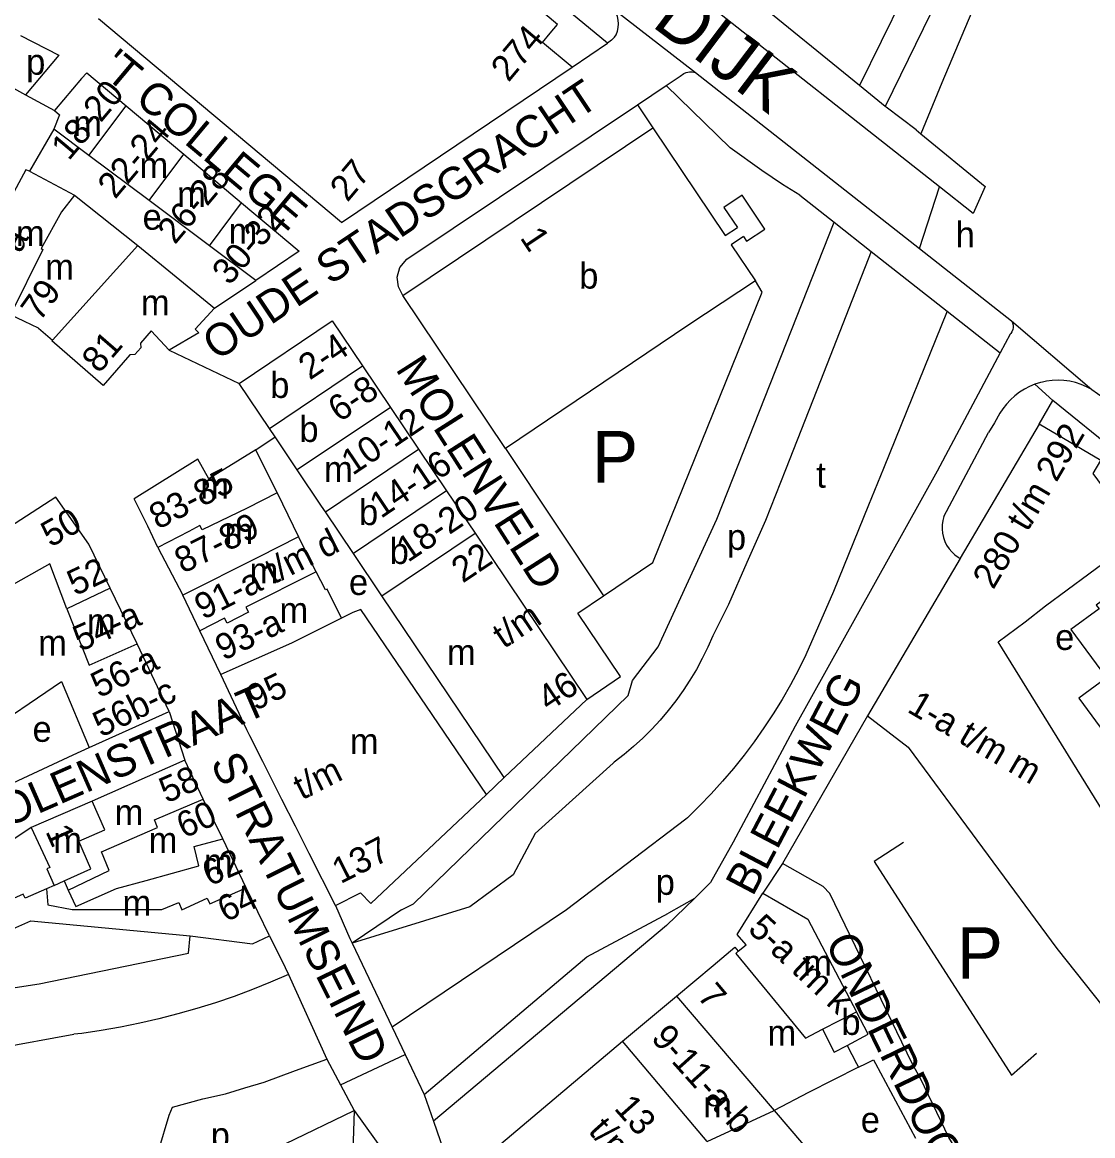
# Model space of a CAD drawing. Extents: x 160673 to 161924, y 382258 to 384145.
# Drawn here: x 161632.6 to 161798.8, y 382888.8 to 383061.6 of the extents above; entities that cross this region are included whole.
import ezdxf

# ---------------------------------------------------------------- set-up
doc = ezdxf.new("R2010")
doc.units = 0
for name, color, linetype in [('BLT_Basislijn', 7, 'Continuous'), ('BLT_Bebouwing', 7, 'Continuous'), ('BLT_Centroide', 7, 'Continuous'), ('BLT_Huisnummer', 7, 'Continuous'), ('BLT_Huisnummer_reeks', 7, 'Continuous'), ('BLT_Onderverdeling_panden', 7, 'Continuous'), ('BLT_Straatnaam', 7, 'Continuous'), ('BLT_Straatnaam_hoofdweg', 7, 'Continuous'), ('BLT_Tekst_parkeren', 7, 'Continuous'), ('BLT_Vlakafsluiter', 7, 'Continuous')]:
    doc.layers.add(name, color=color, linetype=linetype)

msp = doc.modelspace()

# ---------------------------------------------------------------- linework, layer by layer
at = {"layer": 'BLT_Basislijn'}
for p, q in [((161802.97, 383122.97), (161766.55, 383048.54)), ((161774.99, 383036.07), (161709.02, 383088.14)), ((161762.58, 383051.8), (161724.31, 383082.94)), ((161771.33, 383069.65), (161762.58, 383051.8)), ((161632.34, 383059.58), (161638.3, 383056.5)), ((161724.11, 383058.83), (161723.47, 383058.38)), ((161638.3, 383056.5), (161633.15, 383050.37)), ((161737.11, 383053.84), (161771.92, 383026.48)), ((161728.12, 383048.78), (161732.6, 383051.78)), ((161732.6, 383051.78), (161734.76, 383053.23)), ((161766.55, 383048.54), (161762.58, 383051.8)), ((161775.34, 383052.22), (161772.1, 383044.3)), ((161728.12, 383048.78), (161730.52, 383045.21)), ((161766.7, 383048.42), (161766.55, 383048.54)), ((161771.37, 383044.9), (161766.7, 383048.42)), ((161771.37, 383044.9), (161772.1, 383044.3)), ((161772.1, 383044.3), (161782.07, 383036.13)), ((161753.31, 383034.77), (161758.65, 383030.57)), ((161780.23, 383031.93), (161774.99, 383036.07)), ((161758.65, 383030.57), (161764.42, 383026.04)), ((161764.42, 383026.04), (161756.54, 383005.95)), ((161764.42, 383026.04), (161776.19, 383016.8)), ((161771.92, 383026.48), (161786.16, 383015.29)), ((161662.45, 383017.23), (161668.89, 383021.56)), ((161776.19, 383016.8), (161766.3, 382992.38)), ((161776.19, 383016.8), (161784.44, 383010.33)), ((161785.96, 383013.2), (161784.44, 383010.33)), ((161784.44, 383010.33), (161774.64, 382991.92)), ((161792.59, 383002.89), (161789.82, 383005.44)), ((161790.49, 382999.25), (161792.59, 383002.89)), ((161812.15, 382987.08), (161792.59, 383002.89)), ((161668.87, 382995.25), (161671.87, 382997.26)), ((161775.68, 382984.89), (161782.63, 382997.93)), ((161707.66, 382995.45), (161722.86, 382972.59)), ((161655.45, 382954.64), (161657.87, 382947.06)), ((161763.84, 382953.98), (161750.63, 382931.05)), ((161640.54, 382947.93), (161643.01, 382949.05)), ((161631.24, 382943.54), (161640.54, 382947.93)), ((161704.68, 382941.78), (161707.42, 382944.41)), ((161634.03, 382936.61), (161604.03, 382916.71)), ((161750.63, 382931.05), (161747.57, 382926.46)), ((161737, 382925.62), (161732.92, 382923.36)), ((161681.23, 382924.54), (161683.5, 382919.4)), ((161670.99, 382919.84), (161673.46, 382914.91)), ((161683.5, 382919.4), (161683.83, 382918.7)), ((161683.83, 382918.7), (161690.05, 382905.65)), ((161673.46, 382914.91), (161673.96, 382913.83)), ((161673.96, 382913.83), (161679.92, 382900.69)), ((161690.05, 382905.65), (161692.07, 382901.4)), ((161613.51, 382899.59), (161640.65, 382904.53)), ((161682.04, 382896.68), (161692.07, 382901.4)), ((161692.07, 382901.4), (161695.03, 382895.19)), ((161679.92, 382900.69), (161682.04, 382896.68)), ((161682.04, 382896.68), (161684.14, 382892.71)), ((161695.03, 382895.19), (161696.46, 382891.05)), ((161696.46, 382891.05), (161699.83, 382881.27))]:
    msp.add_line(p, q, dxfattribs=at)
for points in [[(161819.83, 383149.18), (161820.21, 383146.13), (161819.64, 383142.5), (161818.55, 383140.46), (161815.64, 383134.73), (161812.46, 383129.75), (161808.28, 383124.28), (161804.19, 383116.19), (161791.81, 383089.44), (161781.57, 383066.96), (161775.34, 383052.22)], [(161723.47, 383058.38), (161712.3, 383067.64), (161706.21, 383072.34)], [(161724.11, 383058.83), (161724.56, 383059.31), (161724.83, 383059.69), (161725.03, 383060.23), (161725.15, 383060.79), (161725.19, 383061.36), (161725.15, 383061.94), (161725.03, 383062.5), (161724.83, 383063.04), (161724.52, 383063.62)], [(161717.99, 383054.63), (161723.47, 383058.38)], [(161734.76, 383053.23), (161735.32, 383053.65), (161735.69, 383053.8), (161736.2, 383053.9), (161736.59, 383053.93), (161737.11, 383053.84)], [(161753.31, 383034.77), (161750.63, 383036.42), (161747.43, 383038.59), (161742.51, 383042.14), (161732.6, 383051.78)], [(161691.7, 383019.23), (161691.01, 383020.57), (161690.8, 383022.04), (161691.24, 383023.57), (161692.35, 383024.84), (161728.12, 383048.78)], [(161691.52, 382923.86), (161693.35, 382924.8), (161726.69, 382957.11), (161727.35, 382959.47), (161731.35, 382964.65), (161740.45, 382984.51), (161758.65, 383030.57)], [(161722.86, 382972.59), (161730.52, 382977.76), (161747.48, 383019.7), (161746.43, 383021.46)], [(161786.16, 383015.29), (161786.31, 383014.95), (161786.42, 383014.61), (161786.44, 383014.26), (161786.39, 383013.91), (161786.25, 383013.58), (161786.05, 383013.29), (161785.96, 383013.2)], [(161756.54, 383005.95), (161751.12, 382992.13), (161747.99, 382984.26), (161745.11, 382977.75), (161742.24, 382971.24), (161739.81, 382966.38)], [(161789.82, 383005.44), (161788.98, 383005.09), (161788.17, 383004.67), (161787.4, 383004.18), (161786.67, 383003.63), (161786, 383003.01), (161785.38, 383002.34), (161784.82, 383001.62), (161784.39, 383000.94)], [(161790.97, 383005.77), (161790.7, 383005.71), (161789.82, 383005.44)], [(161798.63, 383004.62), (161797.83, 383005.05), (161796.98, 383005.4), (161796.11, 383005.68), (161795.22, 383005.89), (161794.32, 383006.01), (161793.41, 383006.05), (161792.49, 383006.02), (161791.59, 383005.9), (161790.97, 383005.77)], [(161798.63, 383004.62), (161801.29, 383002.74), (161803.9, 383000.8), (161806.46, 382998.79), (161808.98, 382996.72), (161811.44, 382994.59), (161813.85, 382992.4), (161816.2, 382990.16), (161818.49, 382987.85), (161820.74, 382985.49), (161822.92, 382983.07), (161825.04, 382980.6), (161827.1, 382978.08), (161827.12, 382978.06)], [(161784.39, 383000.94), (161783.54, 382999.42), (161782.63, 382997.93)], [(161774.64, 382991.92), (161752.58, 382952.34), (161742.97, 382934.38)], [(161766.3, 382992.38), (161763.97, 382986.64), (161758.56, 382973.27), (161754.28, 382963.42)], [(161775.68, 382984.89), (161775.51, 382984.26), (161775.41, 382983.61), (161775.4, 382982.95), (161775.46, 382982.3), (161775.6, 382981.66), (161775.82, 382981.04), (161776.11, 382980.46), (161776.48, 382979.91), (161776.9, 382979.41), (161777.38, 382978.97), (161777.92, 382978.59), (161778.22, 382978.41)], [(161720.25, 382956.52), (161725.51, 382960.06), (161718.85, 382969.89), (161722.86, 382972.59)], [(161739.81, 382966.38), (161739.03, 382964.61), (161738.18, 382962.87), (161737.26, 382961.17), (161736.27, 382959.51), (161735.21, 382957.88), (161734.08, 382956.31), (161732.89, 382954.78), (161731.64, 382953.3), (161730.33, 382951.88), (161728.96, 382950.51), (161727.53, 382949.2), (161726.06, 382947.95), (161724.53, 382946.76), (161724.34, 382946.62)], [(161754.28, 382963.42), (161753.11, 382961.08), (161751.87, 382958.77), (161750.57, 382956.49), (161749.19, 382954.26), (161747.75, 382952.08), (161746.24, 382949.93), (161744.66, 382947.84), (161743.02, 382945.79), (161741.33, 382943.8), (161739.57, 382941.86), (161737.75, 382939.97), (161735.87, 382938.14), (161735.65, 382937.93)], [(161724.34, 382946.62), (161712.22, 382935.7)], [(161735.65, 382937.93), (161717.13, 382923.86), (161690.05, 382905.65)], [(161712.22, 382935.7), (161708.82, 382929.28), (161702.11, 382924.33), (161683.83, 382918.7)], [(161742.97, 382934.38), (161739.46, 382928.12), (161737, 382925.62)], [(161769.43, 382934.29), (161764.88, 382931.36), (161786.17, 382898.18), (161790.07, 382901.6)], [(161784.14, 382876.02), (161776.46, 382888.51), (161772.05, 382897.69), (161770.77, 382900), (161757.99, 382926.38), (161756.93, 382927.5), (161750.63, 382931.05)], [(161737, 382925.62), (161732.65, 382921.44), (161696.46, 382891.05)], [(161691.52, 382923.86), (161683.83, 382918.7)], [(161695.03, 382895.19), (161720.24, 382916.56), (161732.92, 382923.36)], [(161607.9, 382911.66), (161620.7, 382910.15), (161635.24, 382912.37), (161658.42, 382917.15), (161658.7, 382919.84)], [(161673.96, 382913.83), (161671.17, 382912.62), (161668.35, 382911.48), (161665.5, 382910.42), (161662.62, 382909.43), (161659.72, 382908.52), (161656.79, 382907.69), (161653.84, 382906.93), (161650.88, 382906.25), (161647.89, 382905.65), (161644.9, 382905.13), (161641.89, 382904.68), (161640.65, 382904.53)], [(161669.6, 382859.39), (161658.47, 382872.25), (161654.74, 382878.09), (161653.59, 382884.93), (161653.85, 382886.6), (161655.45, 382891.97), (161655.94, 382893.21), (161660.68, 382894.52), (161664.2, 382895.29), (161667.2, 382896.2), (161670.19, 382897.12), (161675.06, 382898.91), (161679.92, 382900.69)], [(161762.41, 382899.43), (161763.63, 382900), (161764.76, 382900.57), (161765.06, 382900), (161771.29, 382888.41)], [(161669.6, 382859.39), (161678.93, 382862.35), (161673.43, 382887.52), (161684.14, 382892.71)], [(161684.14, 382892.71), (161683.96, 382886.35), (161687.67, 382869.67)], [(161684.14, 382892.71), (161689.03, 382885.93), (161706.56, 382820.15)]]:
    msp.add_lwpolyline(points, dxfattribs=at)
at = {"layer": 'BLT_Bebouwing'}
for p, q in [((161682.18, 383030.53), (161644.46, 383062.15)), ((161628.99, 383052.64), (161633.15, 383050.37)), ((161633.15, 383050.37), (161637.63, 383047.94)), ((161648.76, 383048.63), (161657.7, 383041.14)), ((161642.99, 383040.92), (161637.54, 383045)), ((161652.32, 383033.95), (161642.99, 383040.92)), ((161657.7, 383041.14), (161666.68, 383033.6)), ((161633.75, 383038.5), (161640.74, 383034.8)), ((161661.7, 383026.94), (161652.32, 383033.95)), ((161666.68, 383033.6), (161675.62, 383026.09)), ((161668.89, 383021.56), (161661.7, 383026.94)), ((161746.43, 383021.46), (161736.12, 383014.65)), ((161635.17, 383014.15), (161637.34, 383012.28)), ((161666.31, 383005.55), (161680.76, 383015.28)), ((161660.04, 383013.43), (161655.42, 383010.71)), ((161671.87, 382997.26), (161670.99, 382998.57)), ((161790.49, 382999.25), (161778.23, 382978.43)), ((161675.3, 382992.14), (161671.87, 382997.26)), ((161672.22, 382988.57), (161675.49, 382981.73)), ((161652.14, 382983.43), (161650.01, 382987.63)), ((161653.66, 382980.11), (161652.14, 382983.43)), ((161658.48, 382982.59), (161653.66, 382980.11)), ((161653.66, 382980.11), (161657.55, 382972.72)), ((161778.22, 382978.41), (161763.84, 382953.98)), ((161778.23, 382978.43), (161778.22, 382978.41)), ((161650.48, 382965.12), (161646.27, 382973.79)), ((161663.47, 382960.38), (161660.18, 382967.18)), ((161655.45, 382954.64), (161650.48, 382965.12)), ((161667.51, 382951.78), (161663.47, 382960.38)), ((161643.01, 382949.05), (161655.45, 382954.64)), ((161657.87, 382947.06), (161643.48, 382940.73)), ((161660.71, 382941.03), (161657.87, 382947.06)), ((161672.92, 382941), (161669.96, 382946.87)), ((161643.48, 382940.73), (161634.03, 382936.61)), ((161663.78, 382934.85), (161660.71, 382941.03)), ((161675.03, 382936.82), (161672.92, 382941)), ((161677.17, 382932.59), (161675.03, 382936.82)), ((161681.23, 382924.54), (161677.17, 382932.59)), ((161670.99, 382919.84), (161667.41, 382927.29)), ((161658.7, 382919.84), (161668.38, 382918.59)), ((161668.38, 382918.59), (161670.99, 382919.84)), ((161734.18, 382910.46), (161739.86, 382915.21)), ((161725.82, 382903.46), (161734.18, 382910.46)), ((161762.41, 382899.43), (161754.67, 382895.52)), ((161754.67, 382895.52), (161749.33, 382892.73)), ((161749.33, 382892.73), (161757.56, 382883.09))]:
    msp.add_line(p, q, dxfattribs=at)
for points in [[(161717.99, 383054.63), (161713.37, 383058.5), (161714.56, 383059.91), (161715.72, 383061.26), (161631.52, 383131.82), (161630.38, 383130.44), (161629.19, 383129.01), (161624.8, 383132.69)], [(161641.81, 383052.9), (161642.65, 383053.77), (161648.76, 383048.63)], [(161682.18, 383030.53), (161717.99, 383054.63)], [(161641.81, 383052.9), (161637.63, 383047.94)], [(161637.54, 383045), (161633.75, 383038.5)], [(161691.7, 383019.23), (161730.52, 383045.21)], [(161730.52, 383045.21), (161741.71, 383028.51), (161743.64, 383029.77)], [(161640.74, 383034.8), (161650.59, 383026.98)], [(161744.59, 383028.36), (161745.07, 383027.63), (161747.87, 383029.52), (161744.35, 383034.77), (161741.54, 383032.89), (161743.64, 383029.77)], [(161744.59, 383028.36), (161742.67, 383027.09), (161746.43, 383021.46)], [(161650.59, 383026.98), (161662.45, 383017.23)], [(161675.62, 383026.09), (161668.89, 383021.56)], [(161707.66, 382995.45), (161691.7, 383019.23)], [(161662.45, 383017.23), (161659.48, 383014), (161660.04, 383013.43)], [(161635.17, 383014.15), (161630.81, 383016.2)], [(161655.42, 383010.71), (161652.64, 383013.72), (161650.97, 383011.79), (161651.02, 383011.09), (161650.11, 383010.04), (161649.33, 383009.99), (161645.21, 383005.24)], [(161680.76, 383015.28), (161685.46, 383008.28)], [(161736.12, 383014.65), (161707.66, 382995.45)], [(161645.21, 383005.24), (161637.24, 383012.17), (161637.34, 383012.28)], [(161685.46, 383008.28), (161689.81, 383001.81)], [(161670.99, 382998.57), (161666.31, 383005.55)], [(161689.81, 383001.81), (161694.16, 382995.34)], [(161805.8, 382982.14), (161798.86, 382991.57), (161800.06, 382993.62), (161790.49, 382999.25)], [(161668.87, 382995.25), (161661.58, 382990.76), (161659.89, 382993.82), (161650.01, 382987.63)], [(161672.22, 382988.57), (161668.87, 382995.25)], [(161694.16, 382995.34), (161698.5, 382988.87)], [(161679.69, 382985.61), (161679.1, 382986.49), (161675.3, 382992.14)], [(161646.27, 382973.79), (161642.96, 382980.6), (161637.86, 382987.9), (161628.7, 382982.03)], [(161672.22, 382988.57), (161667.54, 382986.19), (161660.57, 382982.82), (161660.22, 382983.49), (161658.48, 382982.59)], [(161698.5, 382988.87), (161702.92, 382982.3)], [(161684.03, 382979.18), (161679.69, 382985.61)], [(161675.49, 382981.73), (161669.31, 382978.6), (161657.55, 382972.72)], [(161678.25, 382976.34), (161675.49, 382981.73)], [(161702.92, 382982.3), (161720.25, 382956.52)], [(161807.7, 382978.53), (161806.59, 382977.71), (161807.17, 382976.91), (161799.33, 382971.16), (161799.76, 382970.57), (161795.41, 382967.37), (161800.93, 382959.85), (161796.63, 382956.69), (161814.15, 382932.83), (161808.29, 382928.52), (161807.9, 382929.17), (161805.55, 382930.84), (161784.09, 382965.44), (161788.29, 382968.53), (161791.47, 382971.05), (161801.54, 382978.47), (161805.48, 382981.47)], [(161688.47, 382972.58), (161684.03, 382979.18)], [(161682.21, 382969.11), (161679.96, 382973.65), (161679.7, 382973.52), (161678.25, 382976.34)], [(161660.18, 382967.18), (161657.55, 382972.72)], [(161707.42, 382944.41), (161688.47, 382972.58)], [(161704.68, 382941.78), (161685.17, 382970.48), (161683.94, 382969.98), (161682.21, 382969.1), (161682.21, 382969.11)], [(161626.19, 382950.83), (161638.7, 382959.29), (161643.01, 382949.05)], [(161720.25, 382956.52), (161707.42, 382944.41)], [(161763.84, 382953.98), (161770.12, 382949.12), (161793.2, 382917.86), (161807.38, 382900), (161809.67, 382897.12)], [(161669.96, 382946.87), (161667.94, 382950.86), (161667.51, 382951.78)], [(161681.23, 382924.54), (161685.14, 382926.49), (161686.75, 382924.83), (161704.68, 382941.78)], [(161634.03, 382936.61), (161636.9, 382930.43), (161636.47, 382930.21), (161637.59, 382927.65)], [(161667.41, 382927.29), (161663.78, 382934.85)], [(161637.59, 382927.65), (161636.38, 382927.12)], [(161636.38, 382927.12), (161633.07, 382925.66), (161632.79, 382926.29), (161626.13, 382923.36), (161627.85, 382919.44), (161633.98, 382922.12), (161658.7, 382919.84)], [(161743.77, 382917.44), (161744.97, 382918.41), (161743.6, 382920.03), (161747.57, 382926.46)], [(161747.57, 382926.46), (161754.56, 382922.39), (161762.14, 382908.03)], [(161739.86, 382915.21), (161743.26, 382918.05), (161743.77, 382917.44)], [(161760.69, 382902.78), (161763.93, 382904.53), (161762.14, 382908.03)], [(161712.38, 382857.06), (161705.26, 382886.11), (161725.82, 382903.46)], [(161760.69, 382902.78), (161762.12, 382900), (161762.41, 382899.43)]]:
    msp.add_lwpolyline(points, dxfattribs=at)
at = {"layer": 'BLT_Onderverdeling_panden'}
for p, q in [((161642.99, 383040.92), (161648.76, 383048.63)), ((161652.32, 383033.95), (161657.7, 383041.14)), ((161661.7, 383026.94), (161666.68, 383033.6)), ((161637.34, 383012.28), (161650.59, 383026.98)), ((161670.99, 382998.57), (161685.46, 383008.28)), ((161689.81, 383001.81), (161675.3, 382992.14)), ((161679.69, 382985.61), (161694.16, 382995.34)), ((161698.5, 382988.87), (161684.03, 382979.18)), ((161688.47, 382972.58), (161702.92, 382982.3)), ((161646.27, 382973.79), (161639.56, 382970.58)), ((161637.59, 382927.65), (161639.13, 382928.38)), ((161756.83, 382905.31), (161762.14, 382908.03)), ((161738.95, 382887.9), (161725.82, 382903.46)), ((161738.95, 382887.9), (161749.33, 382892.73))]:
    msp.add_line(p, q, dxfattribs=at)
for points in [[(161637.63, 383047.94), (161638.43, 383047.26), (161637.54, 383045)], [(161633.75, 383038.5), (161633.21, 383038.69), (161630.58, 383033.9), (161629.99, 383034.22), (161628.94, 383032.15)], [(161640.74, 383034.8), (161638.74, 383032.19), (161635.57, 383026.5), (161635.82, 383026.37), (161630.81, 383016.2)], [(161639.56, 382970.58), (161636.89, 382977.55), (161625.03, 382970.88), (161630.57, 382955.43), (161625.35, 382952.08)], [(161678.25, 382976.34), (161667.36, 382970.82), (161667.76, 382970.04), (161664.44, 382968.36), (161664.05, 382969.14), (161660.18, 382967.18)], [(161639.56, 382970.58), (161643.03, 382961.83), (161650.48, 382965.12)], [(161682.21, 382969.11), (161674.44, 382965.23), (161663.47, 382960.38)], [(161639.13, 382928.38), (161643.3, 382930.2), (161641.39, 382934.51), (161645.45, 382936.29), (161643.48, 382940.73)], [(161639.74, 382926.92), (161646.11, 382929.96), (161644.91, 382932.83), (161653.62, 382936.61), (161653.16, 382937.8), (161660.71, 382941.03)], [(161639.74, 382926.92), (161640.93, 382924.37), (161647.27, 382927.14), (161651.84, 382928.4), (161660.05, 382930.68), (161659.32, 382933.67), (161663.78, 382934.85)], [(161636.38, 382927.12), (161636.61, 382924.64), (161640.37, 382923.88), (161654.3, 382923.91), (161656.94, 382925.01), (161657.42, 382923.85), (161661.32, 382925.65), (161661.74, 382924.76), (161667.41, 382927.29)], [(161639.13, 382928.38), (161639.74, 382926.92)], [(161743.77, 382917.44), (161743.37, 382917.1), (161754.18, 382903.95), (161756.83, 382905.31)], [(161734.18, 382910.46), (161749.33, 382892.73)], [(161756.83, 382905.31), (161758.66, 382901.74), (161760.69, 382902.78)]]:
    msp.add_lwpolyline(points, dxfattribs=at)
at = {"layer": 'BLT_Vlakafsluiter'}
for p, q in [((161724.52, 383063.62), (161737.11, 383053.84)), ((161782.07, 383036.13), (161780.23, 383031.93)), ((161771.92, 383026.48), (161774.99, 383036.07)), ((161786.16, 383015.29), (161798.63, 383004.62)), ((161655.42, 383010.71), (161666.31, 383005.55))]:
    msp.add_line(p, q, dxfattribs=at)

# ---------------------------------------------------------------- texts
at = {"layer": 'BLT_Centroide'}
for s, p in [('p', (161633.24, 383053.48)), ('m', (161640.55, 383043.94)), ('m', (161650.83, 383037.43)), ('m', (161656.67, 383032.92)), ('e', (161651.31, 383029.42)), ('m', (161631.66, 383026.88)), ('m', (161664.67, 383027.25)), ('h', (161777.51, 383026.68)), ('m', (161636.19, 383021.66)), ('b', (161719.08, 383020.28)), ('m', (161651.05, 383016.12)), ('b', (161671.12, 383003.31)), ('b', (161675.65, 382996.48)), ('m', (161679.48, 382990.27)), ('t', (161755.88, 382989.37)), ('m', (161660.27, 382987.69)), ('b', (161684.91, 382983.58)), ('m', (161664.02, 382980.66)), ('p', (161742.01, 382979.72)), ('b', (161689.66, 382977.54)), ('m', (161667.91, 382974.53)), ('e', (161683.34, 382972.72)), ('m', (161672.56, 382968.38)), ('m', (161642.67, 382966.63)), ('e', (161792.95, 382964.19)), ('m', (161635.1, 382963.31)), ('m', (161698.56, 382961.85)), ('e', (161634.23, 382949.93)), ('m', (161683.48, 382948.03)), ('m', (161646.98, 382937)), ('m', (161637.45, 382932.69)), ('m', (161652.26, 382932.69)), ('m', (161660.84, 382929.34)), ('p', (161730.95, 382926.18)), ('m', (161648.19, 382922.94)), ('m', (161753.84, 382913.64)), ('b', (161759.78, 382904.44)), ('m', (161748.3, 382902.77)), ('m', (161738.35, 382891.66)), ('e', (161762.78, 382889.27)), ('p', (161661.89, 382886.88))]:
    msp.add_text(s, height=4, dxfattribs=at).set_placement(p)
at = {"layer": 'BLT_Huisnummer'}
for s, rotation, p in [('1', 303.9033, (161709.79, 383028.17)), ('79', 54.4418, (161635.37, 383015.01)), ('81', 49.014, (161644.54, 383006.97)), ('58', 23.6557, (161655.01, 382940.34)), ('60', 23.6559, (161657.71, 382934.89)), ('1', 294.0086, (161636.18, 382936.04)), ('62', 23.6559, (161661.69, 382927.46)), ('64', 25.6432, (161664.18, 382921.87)), ('7', 310.1644, (161737.26, 382910.36))]:
    msp.add_text(s, height=4, rotation=rotation, dxfattribs=at).set_placement(p)
at = {"layer": 'BLT_Huisnummer_reeks'}
for s, rotation, p in [('274', 50.0162, (161708.1, 383052.19)), ('18-20', 50.0162, (161639.85, 383040)), ('22-24', 50.0162, (161647.05, 383034.04)), ('27', 50.0162, (161683.11, 383033.58)), ('26-28', 50.0162, (161656.33, 383027)), ('30-32', 50.0162, (161664.82, 383020.63)), ('77-a', 62.2811, (161628.74, 383018.78)), ('2-4', 33.8974, (161677.25, 383005.99)), ('6-8', 33.8974, (161681.85, 382999.44)), ('10-12', 33.8974, (161683.91, 382991.19)), ('280 t/m 292', 59.5252, (161783.35, 382973.44)), ('14-16', 33.8974, (161688.3, 382984.51)), ('83-85', 27.2699, (161653.67, 382982.81)), ('18-20', 33.8974, (161692.49, 382977.69)), ('50', 29.3506, (161637.01, 382980.04)), ('87-89', 26.5846, (161657.56, 382975.98)), ('91-a t/m d', 26.7491, (161660.68, 382968.81)), ('22', 33.8974, (161701, 382974.48)), ('52', 25.5766, (161640.84, 382972.52)), ('54-a', 23.8059, (161641.64, 382963.89)), ('t/m', 33.8974, (161707.38, 382964.3)), ('93-a', 25.9588, (161663.85, 382962.47)), ('56-a', 26.2199, (161644.56, 382956.67)), ('95', 25.9588, (161668.77, 382954.68)), ('46', 33.8974, (161714.35, 382954.53)), ('56b-c', 26.2223, (161644.87, 382950.56)), ('1-a t/m m', 329.5252, (161769.81, 382954.67)), ('t/m', 26.8713, (161676.03, 382940.83)), ('137', 26.8713, (161682.03, 382927.82)), ('5-a tm k', 316.9354, (161745.09, 382920.65)), ('9-11-a-b', 311.7795, (161730.09, 382903.85)), ('13', 311.7795, (161724.36, 382892.97)), ('t/m', 311.7795, (161720.35, 382889.44))]:
    msp.add_text(s, height=4, rotation=rotation, dxfattribs=at).set_placement(p)
at = {"layer": 'BLT_Straatnaam'}
for s, height, rotation, p in [("'T COLLEGE", 5, 320.0363, (161644.38, 383054)), ('OUDE STADSGRACHT', 5, 33.7986, (161662.83, 383008.97)), ('MOLENVELD', 5, 302.5496, (161690.48, 383007.8)), ('BLEEKWEG', 5, 62.296, (161746.01, 382925.79)), ('MOLENSTRAAT', 5, 23.6553, (161625.15, 382934.35)), ('STRATUMSEIND', 4.9999, 296.3412, (161661.77, 382946.74)), ('ONDERDOOR', 5, 295.9019, (161757.2, 382918.81))]:
    msp.add_text(s, height=height, rotation=rotation, dxfattribs=at).set_placement(p)
at = {"layer": 'BLT_Straatnaam_hoofdweg'}
msp.add_text('VESTDIJK', height=8, rotation=322.9152, dxfattribs=at).set_placement((161707.87, 383077.97))
at = {"layer": 'BLT_Tekst_parkeren'}
for p in [(161721.09, 382990.18), (161777.7, 382913.15)]:
    msp.add_text('P', height=8, dxfattribs=at).set_placement(p)

doc.saveas('drawing.dxf')
